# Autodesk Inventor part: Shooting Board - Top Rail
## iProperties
Created: 2010-08
Part Number: Shooting Board - Top Rail
Material: Default
Document SubType Name: Modeling
Designer: Paul Munford
Density: 1 g/cm^3
Length: 500 mm
Width: 125 mm
Thickness: 18 mm
Author: Paul Munford
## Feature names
1. Extrusion1
